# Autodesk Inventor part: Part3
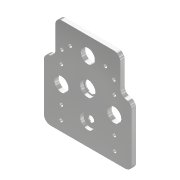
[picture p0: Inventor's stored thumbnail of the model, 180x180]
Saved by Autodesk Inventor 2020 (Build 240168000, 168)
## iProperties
Created: 2020-10
Part Number: Part3
Material: Aluminum 6061
Document SubType Name: Modeling
Designer: Greg
Mass: 241.862 g
Surface Area: 351.051 cm^2
Volume: 89.5784 cm^3
Density: 2.7 g/cm^3
Appearance: Aluminum - Polished
Author: Greg
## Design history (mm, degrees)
sketch "Sketch1"
  geometry: L1 (0, 0)-(127, 0); L2 (127, 0)-(127, 139.7); L3 (127, 139.7)-(0, 139.7); L4 (0, 139.7)-(0, 0)
  constraints: 8 end point, 2 parallel, 1 horizontal, 1 perpendicular
  dimensions: "d0" = 127 distance of L3.end L2.end; "d1" = 139.7 distance of L2.end L1.end
extrude "Extrusion1" new body sketch "Sketch1" distance "d2" = 6.35; taper "d3" = 0 deg
sketch "Sketch2"
  geometry: L1 (0, 0)-(127, 0) reference; L2 (127, 139.7)-(0, 139.7) reference; 2 further points
  constraints: 1 midpoint, 1 vertical alignment
  dimensions: "d4" = 73.3044 distance from line of L1 point (63.5, 73.304)
hole "Hole1" sketch "Sketch2" at (63.5, 73.304) diameter "d5" = 17.78; stored, may be unused: countersink angle "d9" = 82 deg, drill point angle "d11" = 118 deg; dims "d6" = 15.875, "d7" = 15.875, "d8" = 4.826, "d10" = 25.4
sketch "Sketch3"
  geometry: C1 r 8.89 at (63.5, 73.304) reference; 4 further points
  constraints: 1 horizontal alignment, 1 vertical alignment
  dimensions: "d12" = 40.6908 distance of C1.centre point (63.5, 113.995); "d13" = 40.6908 distance of point (25.282, 59.334) C1.centre; "d14" = 40.6908 distance of point (101.718, 59.334) C1.centre; "d15" = 13.97 vertical distance of point (101.718, 59.334) C1.centre
hole "Hole2" sketch "Sketch3" at (63.5, 113.995), (25.282, 59.334), (101.718, 59.334) diameter "d16" = 20.32; stored, may be unused: countersink angle "d20" = 82 deg, drill point angle "d22" = 118 deg; dims "d17" = 15.875, "d18" = 15.875, "d19" = 4.826, "d21" = 25.4
sketch "Sketch4"
  geometry: C1 r 8.89 at (63.5, 73.304) reference; 2 further points
  constraints: 1 vertical alignment
  dimensions: "d23" = 40.6908 distance of point (63.5, 32.614) C1.centre
hole "Hole3" sketch "Sketch4" at (63.5, 32.614) diameter "d24" = 8.6106; stored, may be unused: countersink angle "d28" = 82 deg, drill point angle "d30" = 118 deg; dims "d25" = 15.875, "d26" = 15.875, "d27" = 4.826, "d29" = 25.4
sketch "Sketch5"
  geometry: C1 r 8.89 at (63.5, 73.304) reference; C2 r 11.113 at (63.5, 73.304); C3 r 11.113 at (63.5, 32.614); C4 r 4.305 at (63.5, 32.614) reference; 1 further point
  constraints: 2 centre point, 1 coincident, 1 concentric
  dimensions: "d31" = 22.225 diameter of C2; "d32" = 22.225 diameter of C3
extrude "Extrusion2" cut sketch "Sketch5" distance "d33" = 4.7625; taper "d34" = 0 deg
sketch "Sketch6"
  geometry: L1 (127, 0)-(127, 139.7) reference; L2 (127, 139.7)-(0, 139.7) reference; L3 (0, 139.7)-(0, 0) reference; L4 (0, 0)-(127, 0) reference; L5 (25.908, 103.2)-(101.092, 103.2); L6 (24.854, 14.3)-(102.146, 14.3); C1 r 11.113 at (63.5, 73.304) reference; C2 r 11.113 at (63.5, 32.614) reference; C3 r 10.16 at (25.282, 59.334) reference; C4 r 10.16 at (63.5, 113.995) reference; C5 r 10.16 at (101.718, 59.334) reference; 9 further points
  constraints: 6 vertical alignment, 4 end point, 4 horizontal alignment, 2 horizontal, 2 midpoint
  dimensions: "d35" = 25.4 distance of C4.centre point (38.1, 113.995); "d36" = 25.4 distance of point (88.9, 113.995) C4.centre; "d37" = 25.4 distance of C5.centre point (101.718, 84.734); "d38" = 25.4 distance of point (101.718, 33.934) C5.centre; "d39" = 25.4 distance of C3.centre point (25.282, 33.934); "d40" = 25.4 distance of point (25.282, 84.734) C3.centre; "d41" = 88.9 vertical distance of L6.end L5.end; "d42" = 18.3134 vertical distance of L6.end C2.centre; "d43" = 75.184 distance of L5.start L5.end; "d44" = 77.2922 distance of L6.start L6.end
hole "Hole4" sketch "Sketch6" at (38.1, 113.995), (88.9, 113.995), (25.282, 84.734), (25.282, 33.934), (101.718, 84.734), (101.718, 33.934), (24.854, 14.3), (102.146, 14.3), (101.092, 103.2), (25.908, 103.2) diameter "d45" = 4.9784; stored, may be unused: countersink angle "d49" = 82 deg, drill point angle "d51" = 118 deg; dims "d46" = 15.875, "d47" = 15.875, "d48" = 4.826, "d50" = 25.4
sketch "Sketch7"
  geometry: L1 (0, 139.7)-(16.51, 139.7); L2 (16.51, 139.7)-(16.51, 87.274); L3 (16.51, 87.274)-(0, 87.274); L4 (0, 87.274)-(0, 139.7); L5 (127, 0)-(127, 139.7) reference; L6 (127, 139.7)-(110.49, 139.7); L7 (110.49, 139.7)-(110.49, 87.274); L8 (110.49, 87.274)-(127, 87.274); L9 (127, 87.274)-(127, 139.7); C1 r 8.89 at (63.5, 73.304) reference; 3 further points
  constraints: 16 end point, 4 parallel, 2 horizontal, 2 perpendicular, 1 coincident, 1 collinear, 1 horizontal alignment
  dimensions: "d52" = 93.98 distance between parallel lines of L7 L2; "d53" = 13.97 distance from line of C1.centre L8
extrude "Extrusion3" cut sketch "Sketch7" extent not by distance; stored distance "d54" = 0; taper "d55" = 0 deg
fillet "Fillet1" dims "d56" = 9.525
body "Solid1"
node "Projected Loop1"
